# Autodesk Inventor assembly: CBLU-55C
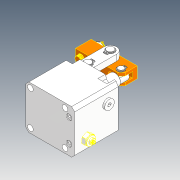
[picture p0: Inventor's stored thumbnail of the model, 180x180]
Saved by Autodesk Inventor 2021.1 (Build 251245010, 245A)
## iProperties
Created: 2019-05
Part Number: CBLU-55C
Description: STEP AP214
Document SubType Name: Assembly
Designer: user
Title: CBLU-55C.STEP
Revision Number: ÈÎºÎ
Sending System: SolidWorks 2016
Preprocessor: SwSTEP 2.0
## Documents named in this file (13)
- D:\Vault_2016\Projekty\Clamptek\Hydraulic\CBLU\CBLU-55\Inventor\CBLU-55C\CBLU-55C.iam
- D:\Vault_2016\Projekty\Clamptek\Hydraulic\CBLU\CBLU-55\Inventor\CBLU-55C\CBLU-55C±¾Ìå_1_1.ipt
- D:\Vault_2016\Projekty\Clamptek\Hydraulic\CBLU\CBLU-55\Inventor\CBLU-55C\changxiao.ipt
- D:\Vault_2016\Projekty\Clamptek\Hydraulic\CBLU\CBLU-55\Inventor\CBLU-55C\duanxiao.ipt
- D:\Vault_2016\Projekty\Clamptek\Hydraulic\CBLU\CBLU-55\Inventor\CBLU-55C\huosaigan_2_1.ipt
- D:\Vault_2016\Projekty\Clamptek\Hydraulic\CBLU\CBLU-55\Inventor\CBLU-55C\liangan.ipt
- D:\Vault_2016\Projekty\Clamptek\Hydraulic\CBLU\CBLU-55\Inventor\CBLU-55C\yabi.ipt
- D:\Vault_2016\Projekty\Clamptek\Hydraulic\CBLU\CBLU-55\Inventor\CBLU-55C\kahuang.ipt
- D:\Vault_2016\Projekty\Clamptek\Hydraulic\CBLU\CBLU-55\Inventor\CBLU-55C\kahuang01.ipt
- D:\Vault_2016\Projekty\Clamptek\Hydraulic\CBLU\CBLU-55\Inventor\CBLU-55C\luogan.ipt
- D:\Vault_2016\Projekty\Clamptek\Hydraulic\CBLU\CBLU-55\Inventor\CBLU-55C\luomu.ipt
- D:\Vault_2016\Projekty\Clamptek\Hydraulic\CBLU\CBLU-55\Inventor\CBLU-55C\ÄÚÁù½Ç¶ÂÍ·×îÐÂ1-4_1.ipt
- D:\Vault_2016\Projekty\Clamptek\Hydraulic\CBLU\CBLU-55\Inventor\CBLU-55C\CZL20µ÷ËÙ·§_1_1_1.ipt
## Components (18 placed, 18 different names)
1. CBLU-55C±¾Ìå_1_1_1
2. changxiao_2
3. duanxiao_3
4. huosaigan_2_1_4
5. liangan_5
6. yabi_6
7. liangan_7
8. changxiao_8
9. kahuang_9
10. kahuang_10
11. kahuang_11
12. kahuang_12
13. kahuang01_13
14. kahuang01_14
15. luogan_15
16. luomu_16
17. ÄÚÁù½Ç¶ÂÍ·×îÐÂ1-4_1_17
18. CZL20µ÷ËÙ·§_1_1_1_18
